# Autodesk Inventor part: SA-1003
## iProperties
Created: 2004-11
Part Number: SA-1003
Cost Center: 0 lbmass
Document SubType Name: Modeling
Designer: busseym
Manufacturer: Standard
Standards Organization: Custom
Stock Number: P-1267
Density: 1 g/cm^3
CAGE: 1LJX3
Dept. ID: Product Design
Description #2: ---
Finish #1: ---
Finish #2: ---
Material ID: ---
Project Number: ---
Author: busseym
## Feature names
1. Revolution1
2. Extrusion1
3. Extrusion2
4. Extrusion3
5. Fillet1
6. Fillet2
7. Extrusion4
8. Mirror1
9. Mirror2
